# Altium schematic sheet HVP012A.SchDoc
size 431 x 279 mm; Date: Not shown in title block; ApprovedBy: Not shown in title block; CheckedBy: Not shown in title block; Author: Not shown in title block; CompanyName: Not shown in title block; Engineer: Not shown in title block; Organization: Not shown in title block; Address1: Not shown in title block; Address2: Not shown in title block; Address3: Not shown in title block; Address4: Not shown in title block; DocumentNumber: 1; Revision: Use project parameter SCH_Rev; SheetNumber: 1; SheetTotal: 1; PageSetup: Record=PageOptions¦CenterHorizontal=True¦CenterVertical=True¦PrintScale=0.64¦XCorrection=1.00¦YCorrection=1.00¦PrintKind=0¦BorderSize=5000000¦LeftOffset=0¦BottomOffset=0¦Orientation=2¦PaperLength=1000¦PaperWidth=1000¦Scale=100¦PaperSource=15¦PrintQuality=600¦MediaType=1¦DitherType=10¦PrintScaleMode=1¦PaperKind=Letter
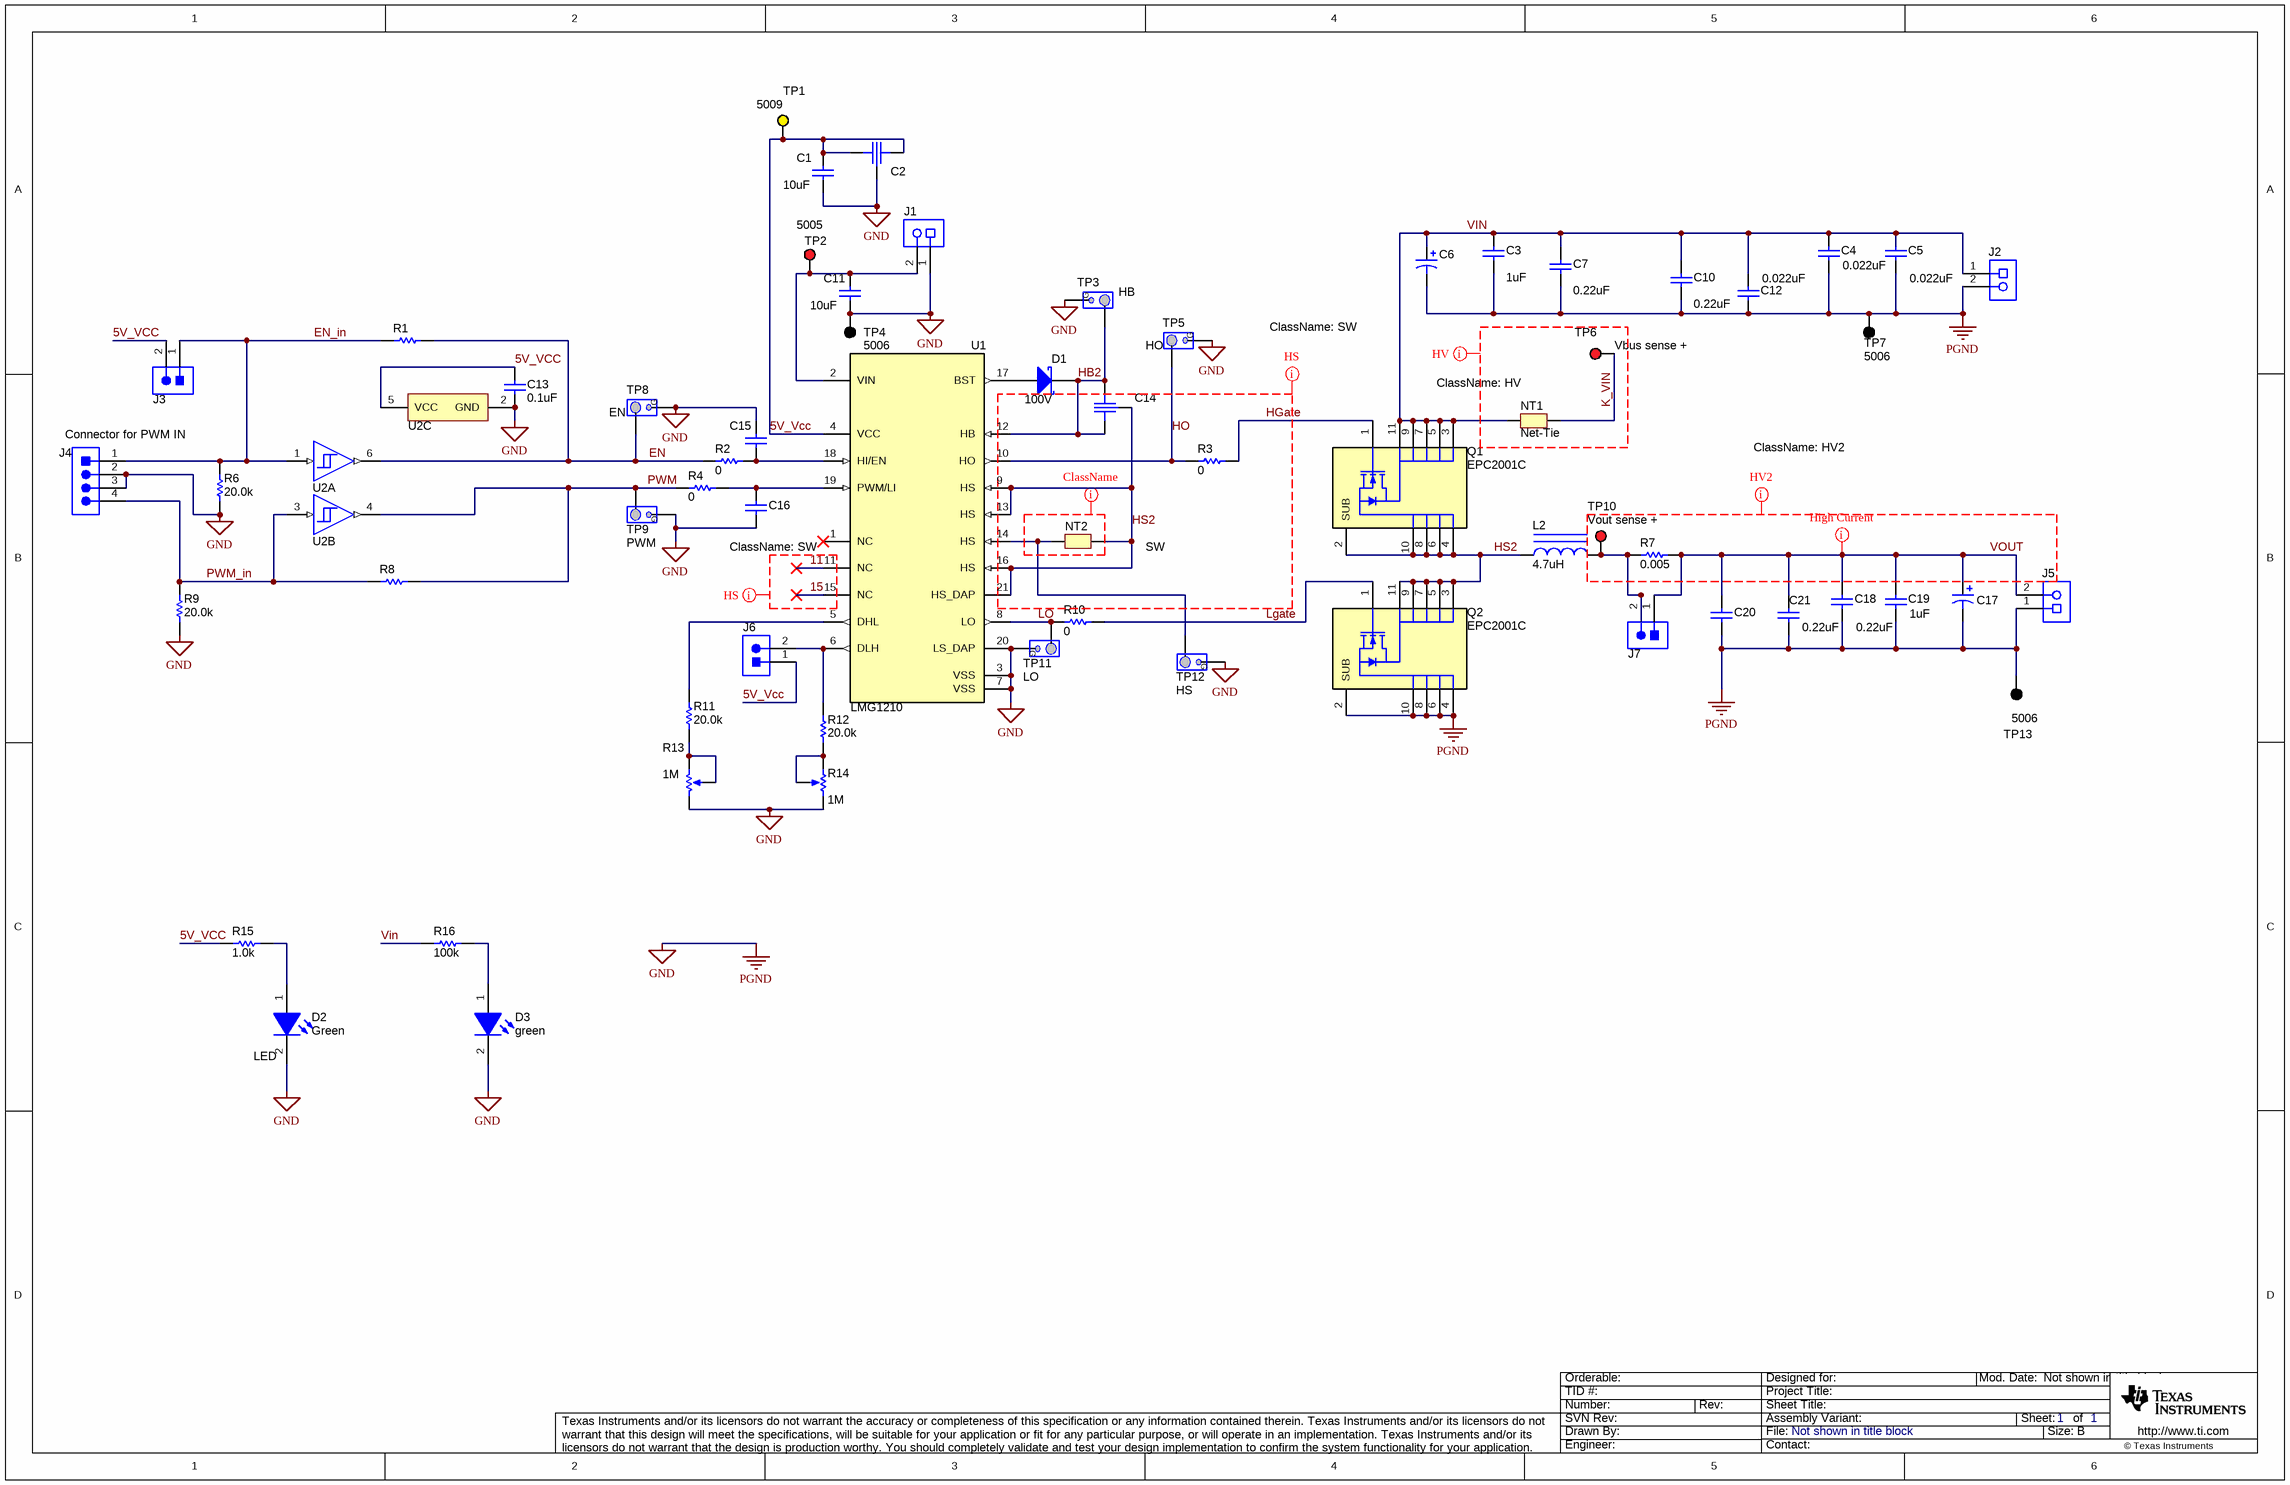
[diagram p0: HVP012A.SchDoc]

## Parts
(Parts that share a designator on the sheet are numbered #1, #2 ... from top to bottom, then left to right.)
C1  ValueDisplayed: 10uF  [1206]  (hidden comment: Capacitor)
C2  Capacitor_Balanced  [YFF18PW]  (value not drawn)
C3  ValueDisplayed: 1uF  [2220_200]  (hidden comment: Capacitor)
C4  ValueDisplayed: 0.022uF  [0805_HV]  (hidden comment: Capacitor)
C5  ValueDisplayed: 0.022uF  [0805_HV]  (hidden comment: Capacitor)
C6  Cap_Polarized  [CAPSMT_62_F60]  (value not drawn)
C7  ValueDisplayed: 0.22uF  [1210_220]  (hidden comment: Capacitor)
C10  ValueDisplayed: 0.22uF  [1210_220]  (hidden comment: Capacitor)
C11  ValueDisplayed: 10uF  [1206]  (hidden comment: Capacitor)
C12  ValueDisplayed: 0.022uF  [0805_HV]  (hidden comment: Capacitor)
C13  ValueDisplayed: 0.1uF  [0603]  (hidden comment: Capacitor)
C14  Capacitor_Balanced  [YFF18PW]  (value not drawn)
C15  Capacitor  [0402]  (value not drawn)
C16  Capacitor  [0402]  (value not drawn)
C17  Cap_Polarized  [CAPSMT_62_H70]  (value not drawn)
C18  ValueDisplayed: 0.22uF  [1210_220]  (hidden comment: Capacitor)
C19  ValueDisplayed: 1uF  [2220_200]  (hidden comment: Capacitor)
C20  Capacitor  [1210_220]  (value not drawn)
C21  ValueDisplayed: 0.22uF  [1210_220]  (hidden comment: Capacitor)
D1  value 100V  [SOD-323F]  (hidden comment: BAT46WJ,115)
D2  LED  value Green  [LTST-C170KGKT_Green]
D3  green  [LTST-C170KGKT_Green]
J1  Receptacle_2x1  [On-Shore_OSTVN02A150]  (value not drawn)
J2  Receptacle_2x1  [TEC_282841-2]  (value not drawn)
J3  Header_2x1  [Sullins_Gxx02SAAN]  (value not drawn)
J4  Header_4x1  [TE_5-146278-4]  (value not drawn)
J5  Receptacle_2x1  [TEC_282841-2]  (value not drawn)
J6  Header_2x1  [Sullins_Gxx02SAAN]  (value not drawn)
J7  Header_2x1  [Sullins_Gxx02SAAN]  (value not drawn)
L2  ValueDisplayed: 4.7uH  [XAL8080]  (hidden comment: Inductor_Iron)
NT1  Net-Tie  [Net-Tie_10milWide_30milLong]  (net tie, no BOM)
NT2  Net-Tie  [Net-Tie_10milWide_30milLong]  (value not drawn)  (net tie, no BOM)
Q1  EPC2001C  [EPC2001]
Q2  EPC2001C  [EPC2001]
R1  Resistor  [0402]  (value not drawn)
R2  ValueDisplayed: 0  [0402]  (hidden comment: Resistor)
R3  ValueDisplayed: 0  [0201]  (hidden comment: Resistor)
R4  ValueDisplayed: 0  [0402]  (hidden comment: Resistor)
R6  ValueDisplayed: 20.0k  [0402]  (hidden comment: Resistor)
R7  ValueDisplayed: 0.005  [0612]  (hidden comment: PRL1632-R005-F-T1)
R8  Resistor  [0402]  (value not drawn)
R9  ValueDisplayed: 20.0k  [0402]  (hidden comment: Resistor)
R10  ValueDisplayed: 0  [0201]  (hidden comment: Resistor)
R11  ValueDisplayed: 20.0k  [0201]  (hidden comment: Resistor)
R12  ValueDisplayed: 20.0k  [0201]  (hidden comment: Resistor)
R13  value 1M  [TRIM_3224X]  (hidden comment: Potentiometer)
R14  value 1M  [TRIM_3224X]  (hidden comment: Potentiometer)
R15  value 1.0k  [0603]  (hidden comment: Resistor)
R16  ValueDisplayed: 100k  [1206]  (hidden comment: Resistor)
TP1  5009  [Keystone5009]
TP2  5005  [Keystone5005]
TP3  HB  [TESTPOINT_PIGTAIL]  (no BOM)
TP4  5006  [Keystone5006]
TP5  HO  [TESTPOINT_PIGTAIL]  (no BOM)
TP6  Vbus sense +  [Keystone5000]
TP7  5006  [Keystone5006]
TP8  EN  [TESTPOINT_PIGTAIL]  (no BOM)
TP9  PWM  [TESTPOINT_PIGTAIL]  (no BOM)
TP10  Vout sense +  [Keystone5000]
TP11  LO  [TESTPOINT_PIGTAIL]  (no BOM)
TP12  HS  [TESTPOINT_PIGTAIL]  (no BOM)
TP13  5006  [Keystone5006]
U1  LMG1210  [RVR0019A]
U2#1  SN74LVC2G17DBVR  [DBV0006A_N]  (value not drawn)  (parts A,C of 3)
U2#2  SN74LVC2G17DBVR  [DBV0006A_N]  (value not drawn)  (part B of 3)

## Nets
GND: C1.2 C2.3 C3.2 C4.2 C5.2 C6.2(-) C7.2 C10.2 C11.1 C12.2 C13.2 C15.1 C16.2 C17.2(-) C18.2 C19.2 C20.2 C21.2 D2.2(K) D3.2(K) J1.1 J2.2 J4.2 J4.3 J5.1 Q2.2(SUB) Q2.4(S) Q2.6(S) Q2.8(S) Q2.10(S) R6.1 R9.1 R13.3(CW) R14.3(CW) TP3.2 TP4.1 TP5.2 TP7.1 TP8.2 TP9.2 TP11.2 TP12.2 TP13.1 U1.3(VSS) U1.7(VSS) U1.20(LS_DAP) U2#1.2(GND)  [also labelled PGND]
5V_Vcc: C1.1 C2.1 C2.2 C13.1 J3.2 J6.1 R15.1 TP1.1 U1.4(VCC) U2#1.5(VCC)
11: U1.11(NC)
15: U1.15(NC)
EN: R1.2 R2.1 TP8.1 U2#1.6(1Y)
EN_in: J3.1 J4.1 R1.1 R6.2 U2#1.1(1A)
HB2: C14.1 C14.2 D1.1(K) TP3.1 U1.12(HB)
HGate: Q1.1(G) R3.2
HO: R3.1 TP5.1 U1.10(HO)
HS2: C14.3 L2.1 NT2.2 Q1.2(SUB) Q1.4(S) Q1.6(S) Q1.8(S) Q1.10(S) Q2.3(D) Q2.5(D) Q2.7(D) Q2.9(D) Q2.11(D) U1.9(HS) U1.13(HS) U1.16(HS) U1.21(HS_DAP)
K_VIN: NT1.2 TP6.1
Lgate: Q2.1(G) R10.2
LO: R10.1 TP11.1 U1.8(LO)
PWM: R4.1 R8.2 TP9.1 U2#2.4(2Y)
PWM_in: J4.4 R8.1 R9.2 U2#2.3(2A)
Vin: C3.1 C4.1 C5.1 C6.1(+) C7.1 C10.1 C12.1 J2.1 NT1.1 Q1.3(D) Q1.5(D) Q1.7(D) Q1.9(D) Q1.11(D) R16.1
VOUT: C17.1(+) C18.1 C19.1 C20.1 C21.1 J5.2 J7.1 R7.2
NetC11_2: C11.2 J1.2 TP2.1 U1.2(VIN)
NetC15_2: C15.2 R2.2 U1.18(HI/EN)
NetC16_1: C16.1 R4.2 U1.19(PWM/LI)
NetD1_2: D1.2(A) U1.17(BST)
NetD2_1: D2.1(A) R15.2
NetD3_1: D3.1(A) R16.2
NetJ6_2: J6.2 R12.2 U1.6(DLH)
NetJ7_2: J7.2 L2.2 R7.1 TP10.1
NetNT2_1: NT2.1 TP12.1 U1.14(HS)
NetR11_1: R11.1 R13.1(CCW) R13.2(WIPER)
NetR11_2: R11.2 U1.5(DHL)
NetR12_1: R12.1 R14.1(CCW) R14.2(WIPER)

Not connected (* = marked no-connect by the designer): U1 1(NC)*

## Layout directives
mark named High Current: VOUT
net class HV: K_VIN
net class SW: 11, 15, HGate, HO, HS2
net class HV2: VOUT

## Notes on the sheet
- (near J4) Connector for PWM IN

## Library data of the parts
C1 C11 = CMP-0008574-2: CAP, CERM, 10 uF, 25 V, +/- 10%, X7R, 1206; PartNumber: 885012208069; Manufacturer: Wurth Elektronik; Polarized: N; Value: 10uF; U/M: EA; Cap_F: 10µF; Value1: Unknown; VDC_V: 25V; TaMin_C: -55°C; TaMax_C: 125°C; AEC Category: Q200; SizeArea_mm2: 5.12; SizeAreaWB_mm2: 10.92; SizeX_mm: 3.2; SizeY_mm: 1.6; SizeZ_mm: 1.35
C2 C14 = CMP-0002107-2: Feedthru Capacitor, 0.47uF, 6.3V, SMD; PartNumber: YFF18PW0J474M; Manufacturer: TDK; CompType: Filter
C3 C19 = CMP-0009465-2: CAP, CERM, 1 uF, 250 V, +/- 10%, X7R, 2220; PartNumber: GRM55DR72E105KW01L; Manufacturer: MuRata; Polarized: N; Value: 1uF; U/M: EA; Cap_F: 1µF; ESR_ohm: 7.086m; Value1: 0.007086 ohm; VDC_V: 250V; IRMS_A: 2.0605A; TaMin_C: -55°C; TaMax_C: 125°C; Cap_Case: 2220; SizeArea_mm2: 28.5; SizeAreaWB_mm2: 53.9; SizeX_mm: 5.7; SizeY_mm: 5; SizeZ_mm: 2; AEC Category: Q200
C4 C5 C12 = CMP-0008410-2: CAP, CERM, 0.022 uF, 250 V, +/- 10%, X7R, 0805; PartNumber: QMK212B7223KG-T; Manufacturer: Taiyo Yuden; Polarized: N; U/M: EA; Cap_F: 22nF; Value1: Unknown; VDC_V: 250V; TaMin_C: -55°C; TaMax_C: 125°C; Cap_Case: 0805; SizeArea_mm2: 2.5; SizeAreaWB_mm2: 6.75; SizeX_mm: 2; SizeY_mm: 1.25; SizeZ_mm: 1.45; AEC Category: Q200
C6 = CMP-0010616-1: CAP, AL, 22 uF, 20 V, +/- 20%, 0.06 ohm, SMD; PartNumber: APXH200ARA220MF60G; Manufacturer: Chemi-Con; Polarized: Y; CompType: Capacitor; Value: 22uF; U/M: EA; Cap_F: 22µF; VDC_V: 20V; ESR_ohm: 0.06; IRMS_A: 1.65A; TaMin_C: -55°C; TaMax_C: 125°C; Cap_Case: F60; SizeAreaWB_mm2: 77.44; SizeArea_mm2: 46.24; SizeX_mm: 6.8; SizeZ_mm: 6; AEC Category: Q200
C7 C10 C18 C20 C21 = CMP-0009193-2: CAP, CERM, 0.22 uF, 250 V, +/- 10%, X7R, 1210; PartNumber: GRM32DR72E224KW01L; Manufacturer: MuRata; Polarized: N; Value: 0.22uF; U/M: EA; Cap_F: 220nF; Value1: Unknown; VDC_V: 250V; TaMin_C: -55°C; TaMax_C: 125°C; Cap_Case: 1210; SizeArea_mm2: 8; SizeAreaWB_mm2: 14.7; SizeX_mm: 3.2; SizeY_mm: 2.5; SizeZ_mm: 2.2; AEC Category: Q200
C13 = CMP-0007404-4: CAP, CERM, 0.1 uF, 25 V, +/- 10%, X7R, 0603; PartNumber: GRM188R71E104KA01D; Manufacturer: MuRata; Polarized: N; Value: 0.1uF; U/M: EA; Cap_F: 100nF; Value1: Unknown; VDC_V: 25V; TaMin_C: -55°C; TaMax_C: 125°C; AEC Category: Q200; SizeArea_mm2: 1.28; SizeAreaWB_mm2: 4.68; SizeX_mm: 1.6; SizeY_mm: 0.8; SizeZ_mm: 1
C15 C16 = CMP-0006207-2: CAP, CERM, 10 pF, 50 V, +/- 5%, C0G/NP0, 0402; PartNumber: 500R07S100JV4T; Manufacturer: Johanson Technology; Polarized: N; Value: 10pF; U/M: EA; Value1: Unknown; VDC_V: 50V; TaMin_C: -55°C; TaMax_C: 125°C; SizeArea_mm2: 0.5; SizeAreaWB_mm2: 3; SizeX_mm: 1; SizeZ_mm: 0.6; AEC Category: Q200
C17 = CMP-0010617-1: CAP, AL, 47 uF, 20 V, +/- 20%, 0.045 ohm, SMD; PartNumber: APXH200ARA470MH70G; Manufacturer: Chemi-Con; Polarized: Y; CompType: Capacitor; Value: 47uF; U/M: EA; Cap_F: 47µF; VDC_V: 20V; ESR_ohm: 0.045; IRMS_A: 2A; TaMin_C: -55°C; TaMax_C: 125°C; Cap_Case: H70; SizeAreaWB_mm2: 110.25; SizeArea_mm2: 72.25; SizeX_mm: 8.5; SizeZ_mm: 7; AEC Category: Q200
D1 = CMP-0076946-1: Diode, Schottky, 100 V, 0.25 A, SOD-323F; Manufacturer: Nexperia; SizeAreaWB_mm2: 7.875; SizeArea_mm2: 3.125; TJmax_C: 150°C; AEC Category: Q101; SizeZ_mm: 0.8; Green_REACh: Incomplete; Io_A: 2.5dA; Vf_V: 8.5dV; SizeY_mm: 1.25; Value2: 0.85V; Green_Lifecycle: Not Set; U/M: EA; Value1: 0.25A; SizeX_mm: 2.5
D2 = CMP-0002888-1: LED, Green, SMD; Manufacturer: Lite-On; PartNumber: LTST-C170KGKT; Type: AlInGaP; Vf_V: 2V; Io_A: 20mA; Value1: W; U/M: EA
D3 = CMP-0002888-1: LED, Green, SMD; Manufacturer: Lite-On; PartNumber: LTST-C170KGKT; Io_A: 20mA; Value1: W; U/M: EA; Vf_V: 2V; Type: AlInGaP
J1 = CMP-0075076-1: Terminal Block, 2.54mm, 2x1, Brass, TH; PartNumber: OSTVN02A150; Manufacturer: On-Shore Technology; CNHeader: False; CT: True; Green_Lifecycle: Not Set; Green_REACh: Incomplete
J2 J5 = CMP-0054973-1: Terminal Block, 2x1, 5.08mm, TH; PartNumber: 282841-2; Manufacturer: TE Connectivity; CNHeader: FALSE; CT: TRUE; Green_Lifecycle: Active; Green_REACh: Passed
J3 J6 J7 = CMP-0054576-1: Header, 2.54 mm, 2x1, Gold, TH; PartNumber: GBC02SAAN; Manufacturer: Sullins Connector Solutions; CNHeader: TRUE; CT: FALSE
J4 = CMP-0054950-1: Header, 100mil, 4x1, Tin, TH; PartNumber: 5-146278-4; Manufacturer: TE Connectivity; CNHeader: TRUE; CT: FALSE; Green_Lifecycle: Active; Green_REACh: Passed
L2 = CMP-0061062-1: Inductor, Shielded, Composite, 4.7 uH, 10.5 A, 0.00889 ohm, SMD; PartNumber: XAL8080-472ME; Manufacturer: Coilcraft; Value: 4.7uH; Ind_H: 4.7µH; Imax_A: 10.5A; Irms: 10.5A @ 20C rise; Isat: 17.4A @ 20% inductance drop; DCR_ohm: 8.89m; SizeAreaWB_mm2: 107.06; SizeArea_mm2: 69.66; SizeX_mm: 8.1; SizeY_mm: 8.6; SizeZ_mm: 8; AEC Category: Q200; Green_Lifecycle: Not Set; Green_REACh: Incomplete
NT1 NT2 = CMP-0078142-1: Single point connection between nets.
Q1 Q2 = CMP-0000972-2: MOSFET, N-CH, 100 V, 36 A, 4.105x1.632mm; Alternate Manufacturer: None; Manufacturer: EPC; SizeZ_mm: 0.815; ChType: N; Value2: 7.5 nC; VdsMax_V: 100V; SizeX_mm: 1.632; SizeAreaWB_mm2: 13.43636; SizeY_mm: 4.105; Vgs_V: 6V; QgTyp_nC: 7.5; Value: 100V; SizeArea_mm2: 6.69936; AEC Category: Q101; IdsMax_A: 36A; U/M: EA
R1 R2 R4 R8 = CMP-0026992-3: RES, 0, 5%, 0.1 W, AEC-Q200 Grade 0, 0402; PartNumber: ERJ-2GE0R00X; Manufacturer: Panasonic; Value: 0; Value_Code: 0000; Power_W: 100mW; Value2: 0.1W; VDC_V: 50V; TempCo: 600 ppm/C; EIA_Code: E24; AEC Category: Q200; AEC Qualified: Y; SizeArea_mm2: 0.5; SizeAreaWB_mm2: 3; SizeX_mm: 1; SizeZ_mm: 0.6
R3 R10 = CMP-0027011-4: RES, 0, 5%, 0.05 W, AEC-Q200 Grade 1, 0201; PartNumber: ERJ-1GE0R00C; Manufacturer: Panasonic; Value: 0; Value_Code: 0000; Power_W: 50mW; Value2: 0.05W; VDC_V: 15V; TempCo: 600 ppm/C; SizeArea_mm2: 0.18; SizeAreaWB_mm2: 2.08; SizeX_mm: 0.6; SizeY_mm: 0.3; SizeZ_mm: 0.26; EIA_Code: E24; AEC Category: Q200; AEC Qualified: Y; AEC Grade: 1
R6 R9 = CMP-0026162-2: RES, 20.0 k, 1%, 0.063 W, AEC-Q200 Grade 0, 0402; PartNumber: CRCW040220K0FKED; Manufacturer: Vishay-Dale; Value: 20.0k; Res_ohm: 20k; Value_Code: 20k0; Power_W: 63mW; Value2: 0.063W; VDC_V: 50V; TempCo: 100 ppm/C; SizeArea_mm2: 0.5; SizeX_mm: 1; SizeZ_mm: 0.6; EIA_Code: E96; AEC Category: Q200; AEC Qualified: Y; AEC Grade: 0
R7 = CMP-0015203-2: RES, 0.005, 1%, 1 W, 0612; Manufacturer: Susumu Co Ltd; Power_W: 1W; TempCo: 350 ppm/C; SizeAreaWB_mm2: 10.92; Value_Code: 5L000; U/M: EA; Value: 0.005; EIA_Code: E96; Res_ohm: 5m; SizeX_mm: 1.6; SizeY_mm: 3.2; SizeZ_mm: 0.85; SizeArea_mm2: 5.12; AEC Category: Q200
R11 R12 = CMP-0027269-3: RES, 20.0 k, 1%, 0.05 W, 0201; PartNumber: CRCW020120K0FKED; Manufacturer: Vishay-Dale; Value: 20.0k; Res_ohm: 20k; Value_Code: 20k0; Power_W: 50mW; Value2: 0.05W; VDC_V: 30V; TempCo: 100 ppm/C; SizeArea_mm2: 0.18; SizeX_mm: 0.6; SizeY_mm: 0.3; SizeZ_mm: 0.26; EIA_Code: E96; AEC Category: Q200; AEC Qualified: N
R13 R14 = CMP-0002063-2: TRIMMER 1M OHM 0.25W SMD; PartNumber: 3224X-1-105E; Manufacturer: Bourns
R15 = CMP-0025729-4: RES, 1.0 k, 5%, 0.1 W, AEC-Q200 Grade 0, 0603; PartNumber: CRCW06031K00JNEA; Manufacturer: Vishay-Dale; Res_ohm: 1k; Value_Code: 1k00; Power_W: 100mW; Value2: 0.1W; VDC_V: 75V; TempCo: 200 ppm/C; EIA_Code: E24; AEC Category: Q200; AEC Grade: 0; AEC Qualified: Y; SizeArea_mm2: 1.28; SizeX_mm: 1.6; SizeY_mm: 0.8; SizeZ_mm: 1
R16 = CMP-0018574-3: RES, 100 k, 5%, 0.25 W, AEC-Q200 Grade 0, 1206; PartNumber: CRCW1206100KJNEA; Manufacturer: Vishay-Dale; Value: 100k; Power_W: 250mW; Value2: 0.25W; VDC_V: 200V; TempCo: 200 ppm/C; SizeArea_mm2: 5.12; SizeX_mm: 3.2; SizeY_mm: 1.6; SizeZ_mm: 1.35; EIA_Code: E24; AEC Category: Q200; AEC Qualified: Y; AEC Grade: 0
TP1 = CMP-0055146-1: Test Point, Compact, Yellow, TH; Manufacturer: Keystone; ContactFinish: Silver; CNHeader: FALSE; CT: TRUE; Green_Lifecycle: Active; Green_REACh: Passed
TP2 = CMP-0055142-1: Test Point, Compact, Red, TH; Manufacturer: Keystone; CNHeader: FALSE; ContactFinish: Silver; CT: TRUE; Green_Lifecycle: Active; Green_REACh: Passed
TP3 TP5 TP8 TP9 TP11 TP12 = CMP-0003907-1: PIGTAIL; Manufacturer: Texas Instruments; CompType: Test Point
TP4 TP7 TP13 = CMP-0055143-1: Test Point, Compact, Black, TH; Manufacturer: Keystone; CNHeader: FALSE; ContactFinish: Silver; CT: TRUE; Green_Lifecycle: Active; Green_REACh: Passed
TP6 TP10 = CMP-0055137-1: Test Point, Miniature, Red, TH; Manufacturer: Keystone; CNHeader: FALSE; Green_Lifecycle: Active; Green_REACh: Passed; ContactFinish: Silver; CT: TRUE
U1 = CMP-0014092-2: Advanced eGaN FET 300V Half-bridge Drive, RVR0019A (WQFN-19); PartNumber: LMG1210RVR; Manufacturer: Texas Instruments; SizeArea_mm2: 12; SizeAreaWB_mm2: 20; SizeX_mm: 4; SizeY_mm: 3; SizeZ_mm: 0.8; CompType: IC; U/M: EA
U2#1 U2#2 = CMP-0051898-1: Dual Schmitt-Trigger Buffer, DBV0006A, LARGE T&R; Manufacturer: Texas Instruments; F @ Nom Voltage(Max)(Mhz): 150; VCC(Max)(V): 5.5; tpd @ Nom Voltage(Max)(ns): 9.3,5.7,5.4,4.3; Sub-Family: Non-Inverting Buffer/Driver; Output Drive (IOL/IOH)(Max)(mA): 32/-32; Output Type: CMOS; Voltage(Nom)(V): 1.8,2.5,3.3,5; ICC @ Nom Voltage(Max)(mA): 0.01; Schmitt Trigger: Yes; Technology Family: LVC; VCC(Min)(V): 1.65; 3-State Output: No; Rating: Catalog; Bits(#): 2; Input Type: CMOS/TTL; Logic: True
